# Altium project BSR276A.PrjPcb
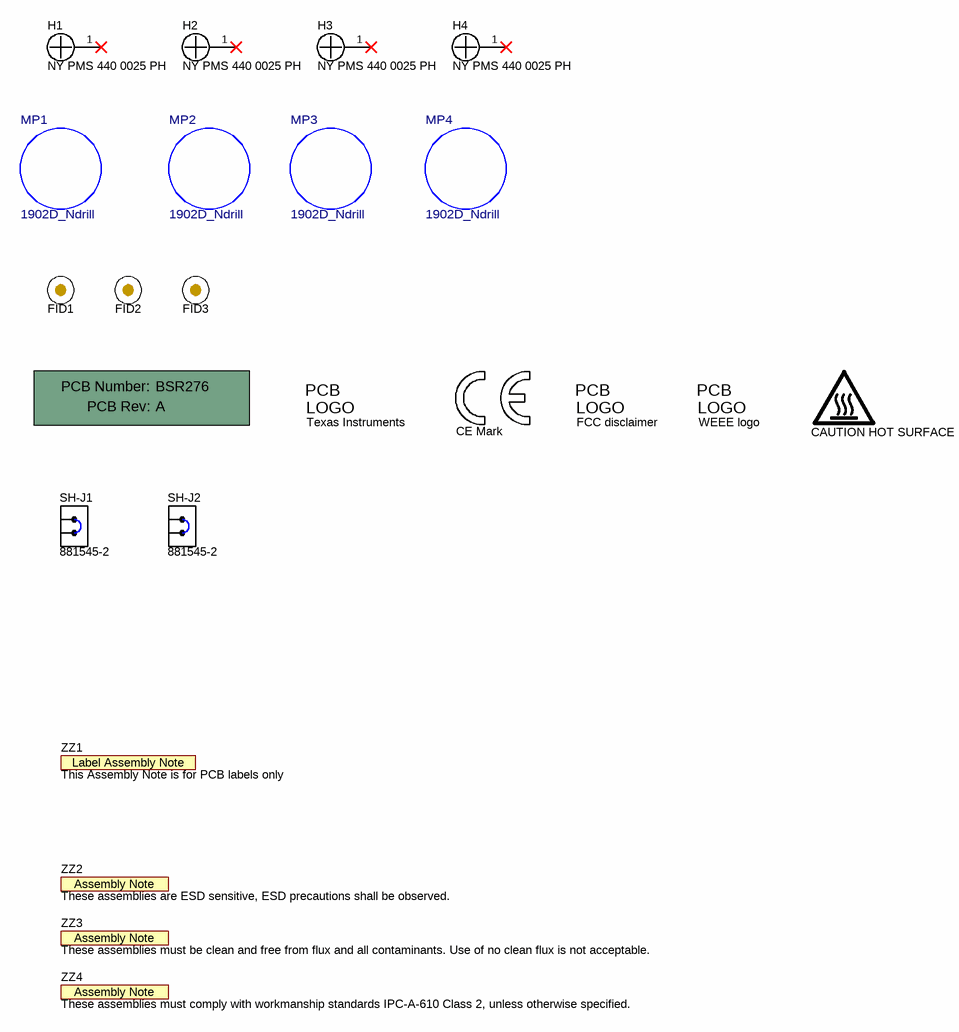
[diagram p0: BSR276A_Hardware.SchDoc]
CopyrightYear: 2023; PCB_Layout: Marshall Beck; PCB_Rev: A; PRJ_Customer: Public Release; PRJ_Engineer: Marshall Beck; PRJ_Number: BSR276; PRJ_Title: TPSM365R15EVM; SCH_Rev: A; TechSupport: http://www.ti.com/support; TID: N/A
2 sheets, 71 parts. Net scope: global (net labels, ports and power ports of the same name join across sheets).
Board file: BSR276A.PcbDoc
Sheets:
  BSR276A_Hardware.SchDoc
  BSR276A.SchDoc

## Sheet BSR276A_Hardware.SchDoc
size 431 x 279 mm; Date: Not shown in title block; ApprovedBy: Not shown in title block; CheckedBy: Not shown in title block; Author: Not shown in title block; CompanyName: Not shown in title block; Engineer: Not shown in title block; Organization: Not shown in title block; Address1: Not shown in title block; Address2: Not shown in title block; Address3: Not shown in title block; Address4: Not shown in title block; DocumentNumber: 3; Revision: Use project parameter SCH_Rev; SheetNumber: 2; SheetTotal: 2; PageSetup: Record=PageOptions¦CenterHorizontal=True¦CenterVertical=True¦PrintScale=1.00¦XCorrection=1.00¦YCorrection=1.00¦PrintKind=0¦BorderSize=5000000¦LeftOffset=0¦BottomOffset=0¦Orientation=2¦PaperLength=1000¦PaperWidth=1000¦Scale=100¦PaperSource=15¦PrintQuality=600¦MediaType=1¦DitherType=10¦PaperKind=Letter¦PrintScaleMode=1

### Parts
!PCB1  Printed Circuit Board  (value not drawn)  (mechanical)
FID1  Fiducial  [Fiducial10-20]  (value not drawn)
FID2  Fiducial  [Fiducial10-20]  (value not drawn)
FID3  Fiducial  [Fiducial10-20]  (value not drawn)
H1  NY PMS 440 0025 PH  [NY PMS 440 0025 PH]
H2  NY PMS 440 0025 PH  [NY PMS 440 0025 PH]
H3  NY PMS 440 0025 PH  [NY PMS 440 0025 PH]
H4  NY PMS 440 0025 PH  [NY PMS 440 0025 PH]
Logo1  CAUTION HOT SURFACE  [IEC_HotSurface_Small]  (no BOM)
Logo2  CE Mark  [CE_Mark_5mm]  (no BOM)
Logo3  Texas Instruments  [TI_Stacked_Overlay_Small]  (no BOM)
Logo4  FCC disclaimer  [FCC_disclaimer]  (no BOM)
Logo5  WEEE logo  [WEEE_Minimum]  (no BOM)
MP1  1902D_Ndrill  [FP-1902D_Ndrill_HEX_STANDOFF-MFG]
MP2  1902D_Ndrill  [FP-1902D_Ndrill_HEX_STANDOFF-MFG]
MP3  1902D_Ndrill  [FP-1902D_Ndrill_HEX_STANDOFF-MFG]
MP4  1902D_Ndrill  [FP-1902D_Ndrill_HEX_STANDOFF-MFG]
SH-J1  881545-2  [TE_881545-2]
SH-J2  881545-2  [TE_881545-2]
ZZ1  This Assembly Note is for PCB labels only  [AssemblyNoteLabel]  (no BOM)
ZZ2  These assemblies are ESD sensitive, ESD precautions shall be observed.  [AssemblyNote]  (no BOM)
ZZ3  These assemblies must be clean and free from flux and all contaminants. Use of no clean flux is not acceptable.  [AssemblyNote]  (no BOM)
ZZ4  These assemblies must comply with workmanship standards IPC-A-610 Class 2, unless otherwise specified.  [AssemblyNote]  (no BOM)

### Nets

Not connected (* = marked no-connect by the designer): H1 1*; H2 1*; H3 1*; H4 1*

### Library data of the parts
!PCB1 = CMP-0003618-2: Manufacturer: Any; PartNumber: BSR276; CompType: PCB
FID1-FID3 = CMP-0077181-1: Fiducial mark.  There is nothing to buy or mount.
H1-H4 = CMP-0003617-1: Machine Screw, Round, #4-40 x 1/4, Nylon, Philips panhead; Manufacturer: B&F Fastener Supply; CompType: Hardware
Logo1 = CMP-0074837-2: IEC 61010-1 Hot Surface Warning; Manufacturer: Texas Instruments; Lib Reference: IEC_HotSurface; CompType: IC; AEC Category: Q200; SymbolCreator: a0412235
Logo2 = CMP-0074844-1: SymbolCreator: a0412235
Logo3 = CMP-0074838-1: Texas Instrument Corporate Signature; SymbolCreator: a0412235; Lib Reference: TI_Logo; Library Reference: Logo
Logo4 = CMP-0074847-1: FCC_disclaimer; Library Reference: Logo
Logo5 = CMP-0074769-1
MP1-MP4 = CMP-0090542-1: Manufacturer: Keystone Electronics; AEC Qualified: No; SizeZ_mm: 19.43mm
SH-J1 SH-J2 = CMP-0003677-2: Shunt, 100mil, Gold plated, Black; Manufacturer: TE Connectivity
ZZ1 = CMP-0003616-3
ZZ2 = CMP-0077236-1
ZZ3 = CMP-0077237-1
ZZ4 = CMP-0077238-1

## Sheet BSR276A.SchDoc
size 431 x 279 mm; Date: Not shown in title block; ApprovedBy: Not shown in title block; CheckedBy: Not shown in title block; Author: Not shown in title block; CompanyName: Not shown in title block; Engineer: Not shown in title block; Organization: Not shown in title block; Address1: Not shown in title block; Address2: Not shown in title block; Address3: Not shown in title block; Address4: Not shown in title block; DocumentNumber: 1; Revision: Use project parameter SCH_Rev; SheetNumber: 1; SheetTotal: 2; PageSetup: Record=PageOptions¦CenterHorizontal=True¦CenterVertical=True¦PrintScale=1.00¦XCorrection=1.00¦YCorrection=1.00¦PrintKind=0¦BorderSize=5000000¦LeftOffset=0¦BottomOffset=0¦Orientation=2¦PaperLength=1000¦PaperWidth=1000¦Scale=100¦PaperSource=15¦PrintQuality=600¦MediaType=1¦DitherType=10¦PaperKind=Letter¦PrintScaleMode=1
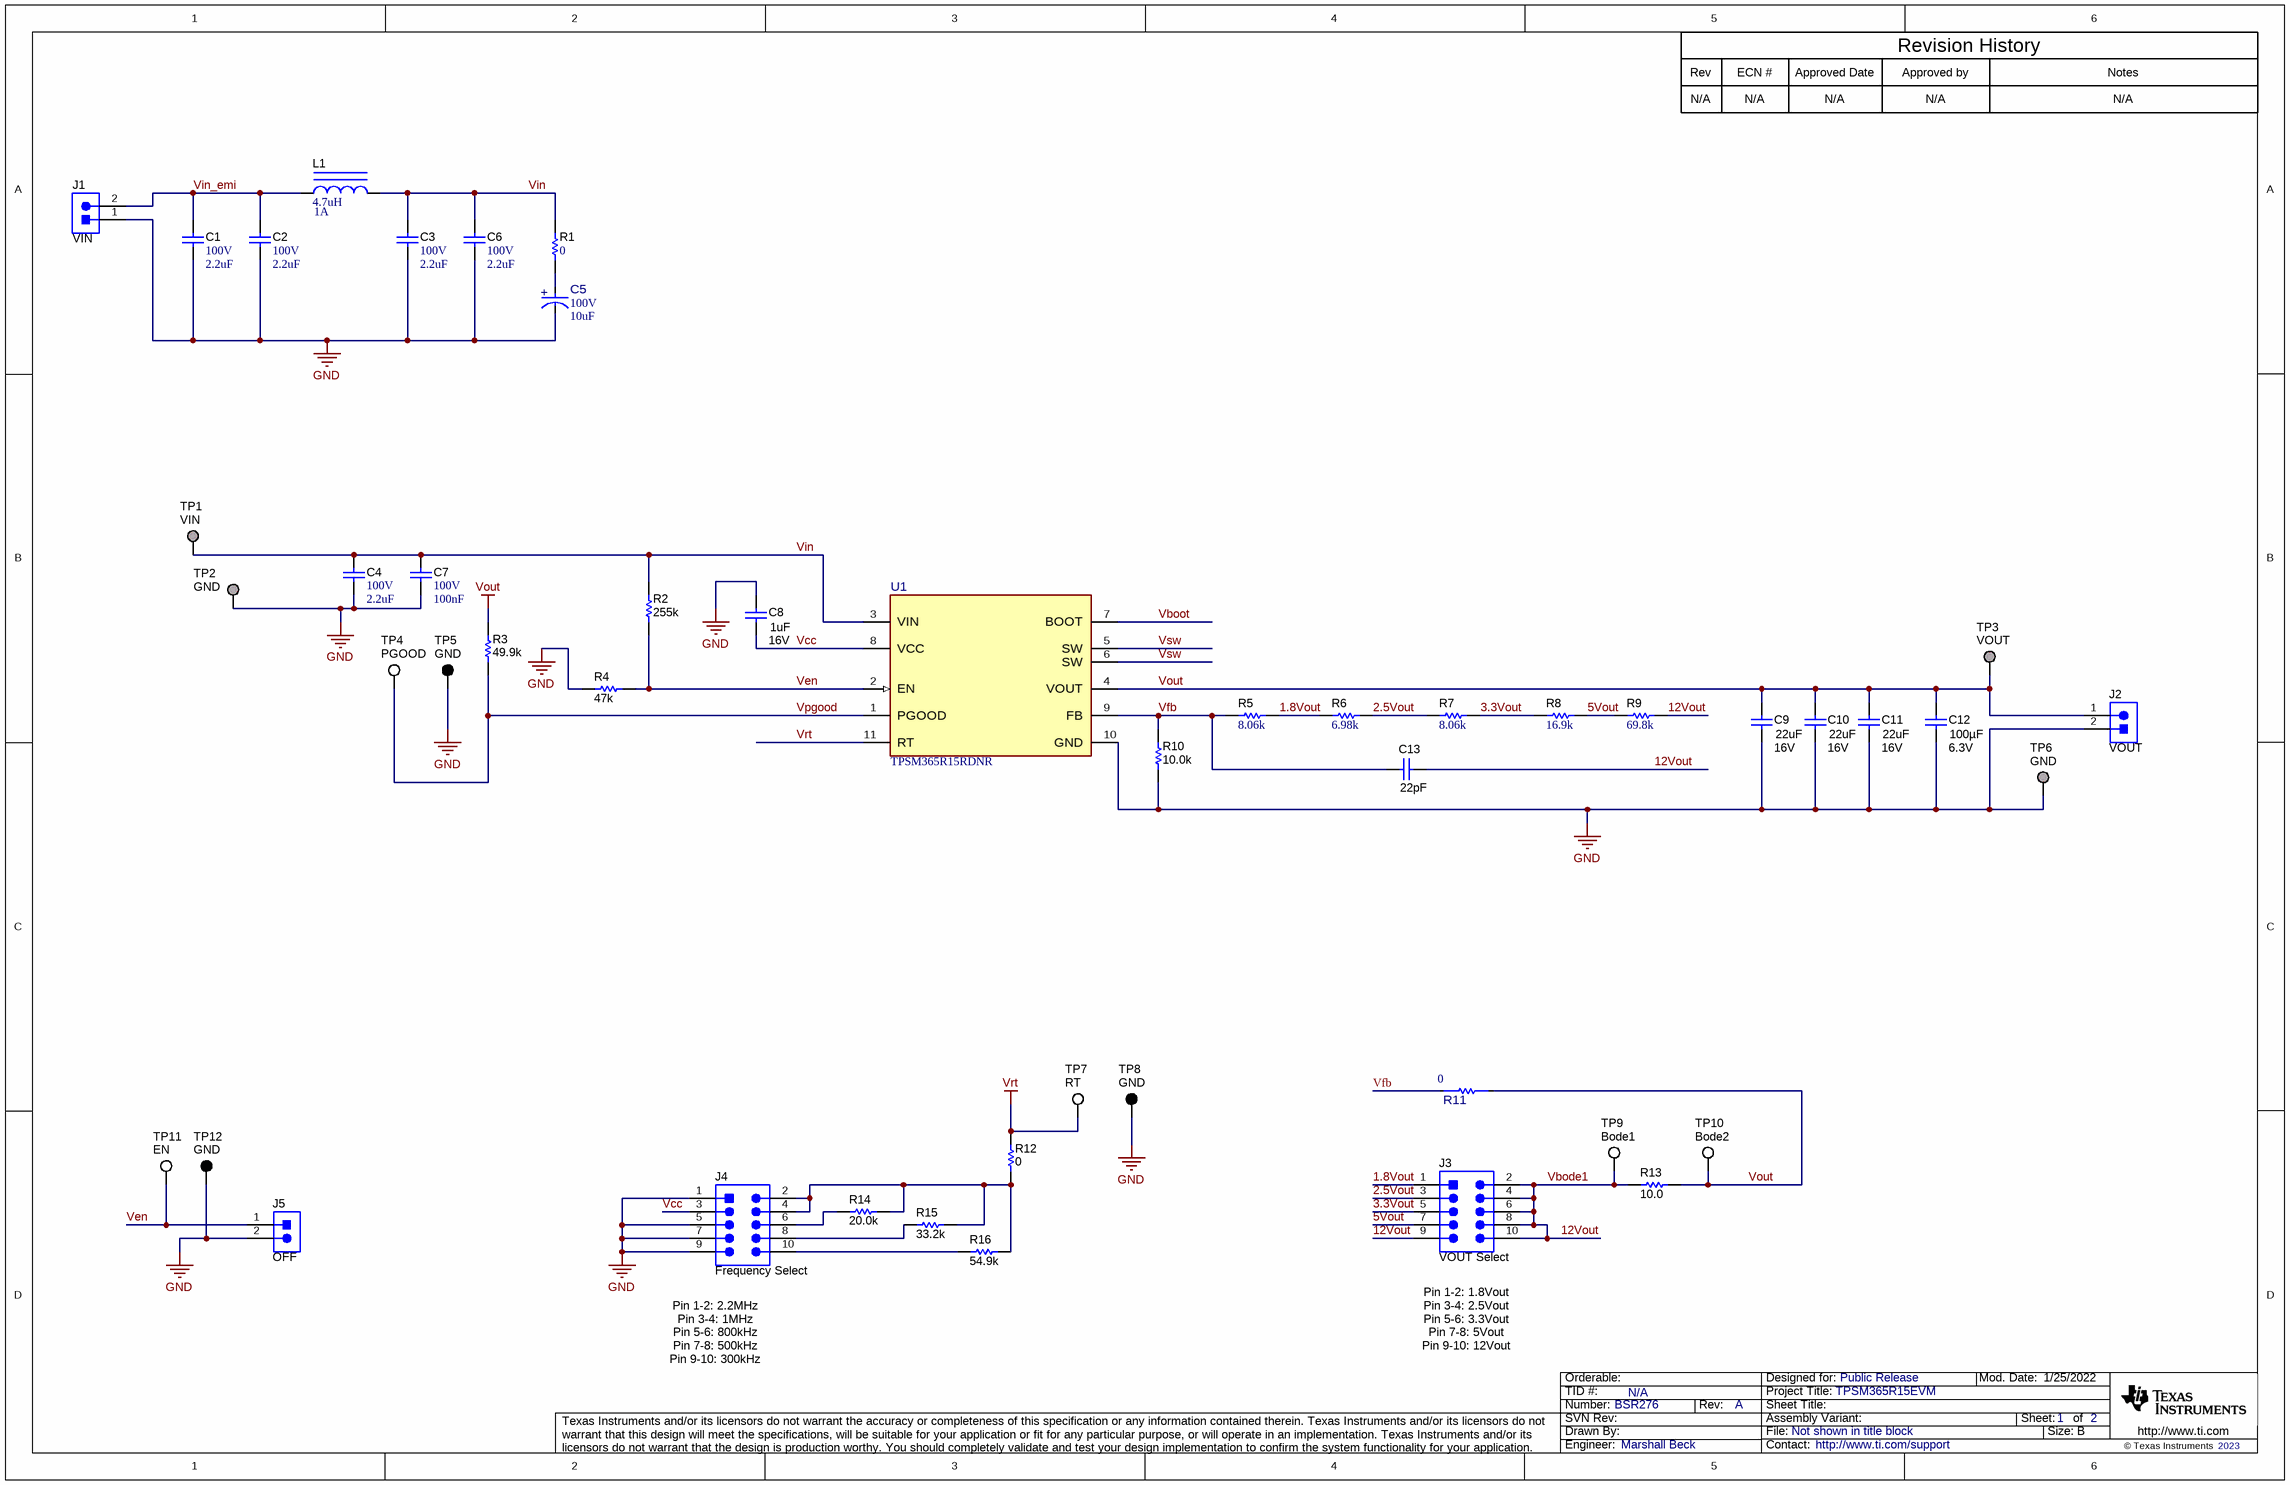
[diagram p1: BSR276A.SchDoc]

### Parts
C1  VDC_V: 100V  ValueDisplayed: 2.2uF  [1210_250L]  (hidden comment: CGA6N3X7R2A225K230AB)
C2  VDC_V: 100V  ValueDisplayed: 2.2uF  [1210_250L]  (hidden comment: CGA6N3X7R2A225K230AB)
C3  VDC_V: 100V  ValueDisplayed: 2.2uF  [1210_250L]  (hidden comment: CGA6N3X7R2A225K230AB)
C4  VDC_V: 100V  ValueDisplayed: 2.2uF  [1210_250L]  (hidden comment: CGA6N3X7R2A225K230AB)
C5  VDC_V: 100V  ValueDisplayed: 10uF  [FP-875075955001_SMT_CAP_8MM3_8MM3-MFG]  (hidden comment: 875075955001)
C6  VDC_V: 100V  ValueDisplayed: 2.2uF  [1210_250L]  (hidden comment: CGA6N3X7R2A225K230AB)
C7  VDC_V: 100V  Cap_F: 100nF  [0805L]  (hidden comment: 885012207128)
C8  VDC_V: 16V  ValueDisplayed: 1uF  [0402L]  (hidden comment: EMK105BJ105KVHF)
C9  VDC_V: 16V  ValueDisplayed: 22uF  [1210_280]  (hidden comment: CGA6P1X7R1C226M250AC)
C10  VDC_V: 16V  ValueDisplayed: 22uF  [1210_280]  (hidden comment: CGA6P1X7R1C226M250AC)
C11  VDC_V: 16V  ValueDisplayed: 22uF  [1210_280]  (hidden comment: CGA6P1X7R1C226M250AC)
C12  VDC_V: 6.3V  ValueDisplayed: 100µF  [1210_270L]  (hidden comment: GRM32EC70J107ME15L)
C13  ValueDisplayed: 22pF  [0402L]  (hidden comment: CGA2B2NP01H220J050BA)
J1  VIN  [Phoenix_1729018]
J2  VOUT  [Phoenix_1729018]
J3  VOUT Select  [CONN_PEC05DAAN]
J4  Frequency Select  [CONN_PEC05DAAN]
J5  OFF  [Samtec_HTSW-102-07-G-S]
L1  Imax_A: 1A  ValueDisplayed: 4.7uH  [WE-MAPI_2512]  (hidden comment: 74438324047)
R1  ValueDisplayed: 0  [0603L]  (hidden comment: RMCF0603ZT0R00)
R2  ValueDisplayed: 255k  [0402L]  (hidden comment: CRCW0402255KFKED)
R3  ValueDisplayed: 49.9k  [0402L]  (hidden comment: CRCW040249K9FKED)
R4  ValueDisplayed: 47k  [0402L]  (hidden comment: CRCW040247K0JNED)
R5  ValueDisplayed: 8.06k  [0402L]  (hidden comment: CRCW04028K06FKED)
R6  ValueDisplayed: 6.98k  [0402L]  (hidden comment: CRCW04026K98FKED)
R7  ValueDisplayed: 8.06k  [0402L]  (hidden comment: CRCW04028K06FKED)
R8  ValueDisplayed: 16.9k  [0402L]  (hidden comment: CRCW040216K9FKED)
R9  ValueDisplayed: 69.8k  [0402L]  (hidden comment: CRCW040269K8FKED)
R10  ValueDisplayed: 10.0k  [0402L]  (hidden comment: CRCW040210K0FKED)
R11  value 0  [FP-RMCF0402ZT0R00_0402-MFG]  (hidden comment: RMCF0402ZT0R00)
R12  ValueDisplayed: 0  [0402L]  (hidden comment: CRCW04020000Z0ED)
R13  ValueDisplayed: 10.0  [0402L]  (hidden comment: CRCW040210R0FKED)
R14  ValueDisplayed: 20.0k  [0402L]  (hidden comment: CRCW040220K0FKED)
R15  ValueDisplayed: 33.2k  [0402L]  (hidden comment: CRCW040233K2FKED)
R16  ValueDisplayed: 54.9k  [0402L]  (hidden comment: CRCW040254K9FKED)
TP1  VIN  [Keystone_5019]
TP2  GND  [Keystone_5019]
TP3  VOUT  [Keystone_5019]
TP4  PGOOD  [Keystone5012]
TP5  GND  [Keystone5011]
TP6  GND  [Keystone_5019]
TP7  RT  [Keystone5012]
TP8  GND  [Keystone5011]
TP9  Bode1  [Keystone5012]
TP10  Bode2  [Keystone5012]
TP11  EN  [Keystone5012]
TP12  GND  [Keystone5011]
U1  TPSM365R15RDNR  [RDN0011A-MFG]

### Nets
GND: C1.2 C2.2 C3.2 C4.2 C5.1(CATHODE) C6.2 C7.2 C8.1 C9.2 C10.2 C11.2 C12.2 J1.1 J2.2 J4.1 J4.5 J4.7 J4.9 J5.2 R4.2 R10.1 TP2.1 TP5.1 TP6.1 TP8.1 TP12.1 U1.10(GND)
Vout: C9.1 C10.1 C11.1 C12.1 J2.1 R3.1 R11.2 R13.2 TP3.1 TP10.1 U1.4(VOUT)
Vrt: R12.2 TP7.1 U1.11(RT)
1.8Vout: J3.1 R5.1 R6.2
2.5Vout: J3.3 R6.1 R7.2
3.3Vout: J3.5 R7.1 R8.2
5Vout: J3.7 R8.1 R9.2
12Vout: C13.1 J3.2 J3.4 J3.6 J3.8 J3.9 J3.10 R9.1 R13.1 TP9.1  [also labelled Vbode1]
Vboot: U1.7(BOOT)
Vcc: C8.2 J4.3 U1.8(VCC)
Ven: J5.1 R2.1 R4.1 TP11.1 U1.2(EN)
Vfb: C13.2 R5.2 R10.2 R11.1 U1.9(FB)
Vin: C3.1 C4.1 C6.1 C7.1 L1.2 R1.2 R2.2 TP1.1 U1.3(VIN)
Vin_emi: C1.1 C2.1 J1.2 L1.1
Vpgood: R3.2 TP4.1 U1.1(PGOOD)
Vsw: U1.5(SW) U1.6(SW)
NetC5_2: C5.2(ANODE) R1.1
NetJ4_2: J4.2 J4.4 R12.1 R14.2 R15.2 R16.2
NetJ4_6: J4.6 R14.1
NetJ4_8: J4.8 R15.1
NetJ4_10: J4.10 R16.1

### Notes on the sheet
- Rev
- N/A
- ECN #
- Approved Date
- Approved by
- Revision History
- Notes
- (near J4) Pin 1-2: 2.2MHz
- (near J3) Pin 1-2: 1.8Vout
- Pin 3-4: 2.5Vout
- Pin 3-4: 1MHz
- Pin 5-6: 800kHz
- Pin 7-8: 500kHz
- Pin 9-10: 300kHz
- Pin 5-6: 3.3Vout
- Pin 7-8: 5Vout
- Pin 9-10: 12Vout

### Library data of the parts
C1-C4 C6 = CMP-0009152-2: CAP, CERM, 2.2 uF, 100 V, +/- 10%, X7R, AEC-Q200 Grade 1,; Manufacturer: TDK; TaMin_C: -55°C; ESR_ohm: 1.73m; Polarized: N; SizeAreaWB_mm2: 14.7; Value1: 0.00173 ohm; U/M: EA; Value: 2.2uF; TaMax_C: 125°C; SizeZ_mm: 2.5; SizeX_mm: 3.2; Cap_Case: 1210_250; SizeArea_mm2: 8; AEC Qualified: Y; Cap_F: 2.2µF; IRMS_A: 5.5932A; AEC Grade: 1; AEC Category: Q200
C5 = CMP-0097784-1: 10µF 100V Aluminum - Polymer Capacitors Radial, Can - SMD 45mOhm 2000 Hrs @ 105°C; Manufacturer: Wurth Electronics; Tolerance_%: 20%; Life: 2000Hours; SizeZ_mm: 12mm; AEC Qualified: No; Esr: 45m; IRMS_A: 1.7A; Dissipation Factor: 12%; Leakage Current: 200uA
C7 = CMP-0750058-1: CAP, CERM, 0.1 µF, 100 V,+/- 10%, X7R, 0805; Manufacturer: Wurth Elektronik; TaMin_C: -55°C; AEC Category: Q200; U/M: EA; SizeY_mm: 1.25; Polarized: N; Value: 0.1uF; SizeX_mm: 2; TaMax_C: 125°C; ValueDisplayed: 0.1µF; SizeArea_mm2: 2.5; Cap_Case: 0805; SizeZ_mm: 1.45; SizeAreaWB_mm2: 6.75
C8 = CMP-0006347-2: CAP, CERM, 1 uF, 16 V, +/- 10%, X5R, 0402; Manufacturer: Taiyo Yuden; TaMin_C: -55°C; Polarized: N; SizeAreaWB_mm2: 3; Value1: Unknown; U/M: EA; Value: 1uF; TaMax_C: 85°C; SizeZ_mm: 0.6; SizeX_mm: 1; SizeY_mm: 0.5; Cap_Case: 0402; CompType: Capacitor; Cap_F: 1µF; AEC Category: Q200
C9-C11 = CMP-0009154-2: CAP, CERM, 22 uF, 16 V, +/- 20%, X7R, AEC-Q200 Grade 1, 1210; Manufacturer: TDK; TaMin_C: -55°C; ESR_ohm: 2.582m; Polarized: N; SizeAreaWB_mm2: 14.7; Value1: 0.002582 ohm; U/M: EA; Value: 22uF; TaMax_C: 125°C; SizeZ_mm: 2.8; SizeX_mm: 3.2; SizeY_mm: 2.5; SizeArea_mm2: 8; CompType: Capacitor; AEC Qualified: Y; Cap_F: 22µF; IRMS_A: 4.57562A; AEC Grade: 1; AEC Category: Q200
C12 = CMP-0083812-2: CAP, CERM, 100 µF, 6.3 V,+/- 20%, X7S, 1210; Manufacturer: MuRata; CompType: Capacitor; AEC Qualified: N; Value: 100uF; SizeAreaWB_mm2: 14.7; SizeArea_mm2: 8; SizeX_mm: 3.2; TaMax_C: 125°C; U/M: EA; SizeZ_mm: 2.7; TaMin_C: -55°C; AEC Category: Q200; SizeY_mm: 2.5; Cap_Case: 1210
C13 = CMP-0006311-2: CAP, CERM, 22 pF, 50 V, +/- 5%, C0G/NP0, AEC-Q200 Grade 1, 0402; Manufacturer: TDK; TaMin_C: -55°C; Polarized: N; SizeAreaWB_mm2: 3; Value1: Unknown; U/M: EA; Value: 22pF; TaMax_C: 125°C; SizeZ_mm: 0.6; SizeX_mm: 1; SizeY_mm: 0.5; Cap_Case: 0402; Value2: 50V; CompType: Capacitor; AEC Qualified: Y; AEC Category: Q200
J1 J2 = CMP-0055486-1: TERM BLOCK 2POS 5mm, TH; Manufacturer: Phoenix Contact; PartNumber: 1729018; CT: TRUE; Green_REACh: Incomplete; CompType: Terminal Block; CNHeader: FALSE; Green_Lifecycle: Not Set
J3 J4 = CMP-0054550-2: Header, 100mil, 5x2, Tin, TH; Manufacturer: Sullins Connector Solutions; PartNumber: PEC05DAAN; Current_A: 3A; Green_Lifecycle: Active; Shrouded: N; Gender: Male; Green_REACh: Passed; Voltage_V: 1.8kV; Row_Count: 2; RowSpacing_mm: 2.54; Cert_UL: Y
J5 = CMP-0075483-1: Header, 100mil, 2x1, Gold, TH; PartNumber: HTSW-102-07-G-S; Manufacturer: Samtec; Green_REACh: Passed; CT: False; Green_Lifecycle: Active; CNHeader: True
L1 = CMP-0064146-1: Inductor, Shielded, Powdered Iron, 4.7 uH, 1 A, 0.345 ohm, SMD; Manufacturer: Wurth Elektronik; Isat: 2.1A @ 20% inductance drop; Irms: 1A @ 40C rise; SizeAreaWB_mm2: 10.5; DCR_ohm: 0.345; Value: 4.7uH; SizeZ_mm: 1.2; SizeX_mm: 2.5; SizeY_mm: 2; SizeArea_mm2: 5; Ind_H: 4.7µH; AEC Qualified: N; AEC Category: Q200
R1 = CMP-0023343-3: RES, 0, 1%, 0.1 W, AEC-Q200 Grade 0, 0603; Manufacturer: Stackpole Electronics Inc; Power_W: 100mW; TempCo: ppm/C; U/M: EA; Value: 0; SizeX_mm: 1.6; SizeY_mm: 0.8; SizeZ_mm: 1; Value2: 0.1W; SizeArea_mm2: 1.28; AEC Qualified: Y; AEC Category: Q200
R2 = CMP-0026199-2: RES, 255 k, 1%, 0.063 W, AEC-Q200 Grade 0, 0402; Manufacturer: Vishay-Dale; Power_W: 63mW; TempCo: 100 ppm/C; Value: 255k; EIA_Code: E96; SizeX_mm: 1; SizeY_mm: 0.5; SizeZ_mm: 0.6; Value2: 0.063W; CompType: Resistor; AEC Qualified: Y; VDC_V: 50V; AEC Category: Q200; AEC Grade: 0
R3 = CMP-0026403-1: RES, 49.9 k, 1%, 0.063 W, 0402; Manufacturer: Vishay-Dale; Power_W: 63mW; TempCo: 100 ppm/C; Value_Code: 49k9; U/M: EA; Value: 49.9k; EIA_Code: E96; SizeX_mm: 1; SizeY_mm: 0.5; SizeZ_mm: 0.6; Value2: 0.063W; CompType: Resistor; VDC_V: 50V; AEC Category: Q200
R4 = CMP-0026935-3: RES, 47 k, 5%, 0.063 W, AEC-Q200 Grade 0, 0402; Manufacturer: Vishay-Dale; Power_W: 63mW; TempCo: 200 ppm/C; Value_Code: 47k0; Value: 47k; EIA_Code: E24; SizeX_mm: 1; SizeY_mm: 0.5; SizeZ_mm: 0.6; Value2: 0.063W; CompType: Resistor; AEC Qualified: Y; VDC_V: 50V; AEC Category: Q200; AEC Grade: 0
R5 R7 = CMP-0026588-2: RES, 8.06 k, 1%, 0.063 W, AEC-Q200 Grade 0, 0402; Manufacturer: Vishay-Dale; Power_W: 63mW; TempCo: 100 ppm/C; Value_Code: 8k06; Value: 8.06k; EIA_Code: E96; SizeX_mm: 1; SizeY_mm: 0.5; SizeZ_mm: 0.6; Value2: 0.063W; CompType: Resistor; AEC Qualified: Y; VDC_V: 50V; AEC Category: Q200; AEC Grade: 0
R6 = CMP-0026518-2: RES, 6.98 k, 1%, 0.063 W, AEC-Q200 Grade 0, 0402; Manufacturer: Vishay-Dale; Power_W: 63mW; TempCo: 100 ppm/C; Value_Code: 6k98; Value: 6.98k; EIA_Code: E96; SizeX_mm: 1; SizeY_mm: 0.5; SizeZ_mm: 0.6; Value2: 0.063W; CompType: Resistor; AEC Qualified: Y; VDC_V: 50V; AEC Category: Q200; AEC Grade: 0
R8 = CMP-0026042-3: RES, 16.9 k, 1%, 0.063 W, AEC-Q200 Grade 0, 0402; Manufacturer: Vishay-Dale; Power_W: 63mW; TempCo: 100 ppm/C; Value_Code: 16k9; Value: 16.9k; EIA_Code: E96; SizeX_mm: 1; SizeY_mm: 0.5; SizeZ_mm: 0.6; Value2: 0.063W; CompType: Resistor; AEC Qualified: Y; VDC_V: 50V; AEC Category: Q200; AEC Grade: 0
R9 = CMP-0026510-1: RES, 69.8 k, 1%, 0.063 W, 0402; Manufacturer: Vishay-Dale; Power_W: 63mW; TempCo: 100 ppm/C; Value_Code: 69k8; U/M: EA; Value: 69.8k; EIA_Code: E96; SizeX_mm: 1; SizeY_mm: 0.5; SizeZ_mm: 0.6; Value2: 0.063W; CompType: Resistor; VDC_V: 50V; AEC Category: Q200
R10 = CMP-0025958-3: RES, 10.0 k, 1%, 0.063 W, AEC-Q200 Grade 0, 0402; Manufacturer: Vishay-Dale; Power_W: 63mW; TempCo: 100 ppm/C; Value_Code: 10k0; Value: 10.0k; EIA_Code: E96; Res_ohm: 10k; SizeX_mm: 1; SizeY_mm: 0.5; SizeZ_mm: 0.6; Value2: 0.063W; CompType: Resistor; AEC Qualified: Y; VDC_V: 50V; AEC Category: Q200; AEC Grade: 0
R11 = CMP-0097070-1: Res Thick Film 0402 0 Ohm Jumper Molded SMD Paper T/R; Manufacturer: Stackpole; Power_W: 63mW; SizeZ_mm: 0.4mm; AEC Qualified: Yes; VDC_V: 50V
R12 = CMP-0026822-3: RES, 0, 5%, 0.063 W, AEC-Q200 Grade 0, 0402; Manufacturer: Vishay-Dale; Power_W: 63mW; TempCo: 200 ppm/C; Value_Code: 0000; Value: 0; EIA_Code: E24; SizeX_mm: 1; SizeY_mm: 0.5; SizeZ_mm: 0.6; Value2: 0.063W; CompType: Resistor; AEC Qualified: Y; VDC_V: 50V; AEC Category: Q200
R13 = CMP-0025963-3: RES, 10.0, 1%, 0.063 W, AEC-Q200 Grade 0, 0402; Manufacturer: Vishay-Dale; Power_W: 63mW; TempCo: 100 ppm/C; Value_Code: 10R0; Value: 10.0; EIA_Code: E96; Res_ohm: 10; SizeX_mm: 1; SizeY_mm: 0.5; SizeZ_mm: 0.6; Value2: 0.063W; CompType: Resistor; AEC Qualified: Y; VDC_V: 50V; AEC Category: Q200; AEC Grade: 0
R14 = CMP-0026162-2: RES, 20.0 k, 1%, 0.063 W, AEC-Q200 Grade 0, 0402; Manufacturer: Vishay-Dale; Power_W: 63mW; TempCo: 100 ppm/C; Value_Code: 20k0; Value: 20.0k; EIA_Code: E96; Res_ohm: 20k; SizeX_mm: 1; SizeY_mm: 0.5; SizeZ_mm: 0.6; Value2: 0.063W; CompType: Resistor; AEC Qualified: Y; VDC_V: 50V; AEC Category: Q200; AEC Grade: 0
R15 = CMP-0026298-2: RES, 33.2 k, 1%, 0.063 W, AEC-Q200 Grade 0, 0402; Manufacturer: Vishay-Dale; Power_W: 63mW; TempCo: 100 ppm/C; Value_Code: 33k2; Value: 33.2k; EIA_Code: E96; SizeX_mm: 1; SizeY_mm: 0.5; SizeZ_mm: 0.6; Value2: 0.063W; CompType: Resistor; AEC Qualified: Y; VDC_V: 50V; AEC Category: Q200; AEC Grade: 0
R16 = CMP-0026449-2: RES, 54.9 k, 1%, 0.063 W, AEC-Q200 Grade 0, 0402; Manufacturer: Vishay-Dale; Power_W: 63mW; TempCo: 100 ppm/C; Value_Code: 54k9; Value: 54.9k; EIA_Code: E96; SizeX_mm: 1; SizeY_mm: 0.5; SizeZ_mm: 0.6; Value2: 0.063W; CompType: Resistor; AEC Qualified: Y; VDC_V: 50V; AEC Category: Q200; AEC Grade: 0
TP1-TP3 TP6 = CMP-0055162-1: Test Point, Miniature, SMT; Manufacturer: Keystone; PartNumber: 5019; CNHeader: FALSE; Green_Lifecycle: Active; Green_REACh: Passed; CT: TRUE
TP4 TP7 TP9-TP11 = CMP-0055149-2: Test Point, Multipurpose, White, TH; Manufacturer: Keystone Electronics; PartNumber: 5012; ContactFinish: Silver; CT: TRUE; CNHeader: FALSE; Green_Lifecycle: Active; Green_REACh: Passed
TP5 TP8 TP12 = CMP-0055148-2: Test Point, Multipurpose, Black, TH; PartNumber: 5011; Manufacturer: Keystone Electronics; CNHeader: FALSE; ContactFinish: Silver; Green_REACh: Passed; Green_Lifecycle: Active; CT: TRUE
U1 = CMP-0098237-1: Synchronous Buck Converter Power Module, QFN-FCMOD11; Manufacturer: Texas Instruments; Standoff Height: 0mm; Number Of Outputs: 1; AEC Qualified: No; Output Type: AdjustableProgrammable; SizeZ_mm: 2.1mm

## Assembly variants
001: not fitted C11 C12 FID1 FID2 FID3 R4 R11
